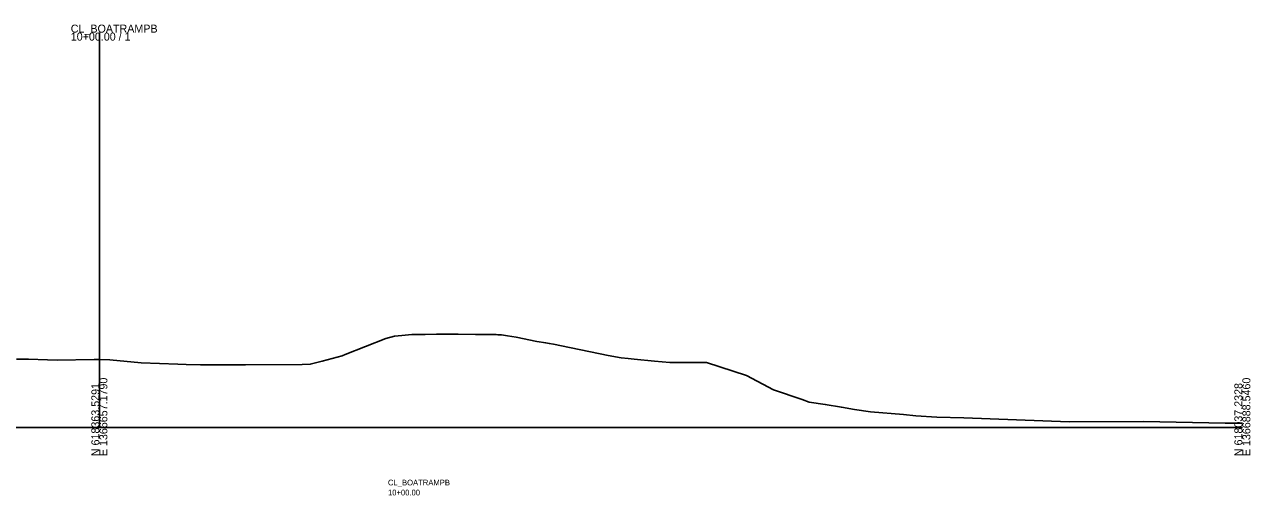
# Model space of a CAD drawing. Extents: x -26 to 803, y -24 to 3192.
# Drawn here: x 373.8 to 802.8, y -23.8 to 141.1 of the extents above; entities that cross this region are included whole.
import ezdxf

# ---------------------------------------------------------------- set-up
doc = ezdxf.new("R2010")
doc.units = 0
for name, color, linetype in [('DESIGN - SHEET - Light Grid', 7, 'Continuous'), ('DESIGN - TYPICAL - Warning Text', 7, 'Continuous'), ('SURVEY - GROUND - Top of Ground', 7, 'Continuous')]:
    doc.layers.add(name, color=color, linetype=linetype)

msp = doc.modelspace()

# ---------------------------------------------------------------- linework, layer by layer
at = {"layer": 'DESIGN - SHEET - Light Grid'}
for p, q in [((400, 0), (400, 138.3)), ((0, 0), (400, 0)), ((400, 0), (800, 0))]:
    msp.add_line(p, q, dxfattribs=at)
at = {"layer": 'SURVEY - GROUND - Top of Ground'}
msp.add_lwpolyline([(370.95, 23.97), (375.17, 23.94), (381.8, 23.71), (385.26, 23.65), (398.23, 23.84), (400, 23.8), (403.65, 23.73), (414.63, 22.64), (427.46, 22.22), (430.4, 22.06), (435.44, 22.03), (451.12, 21.93), (470.93, 22.13), (473.81, 22.15), (477.97, 23.27), (485.02, 25.17), (486.03, 25.65), (500.21, 31.15), (503.27, 32), (505.9, 32.27), (509.33, 32.56), (511.76, 32.63), (512.38, 32.64), (514.05, 32.65), (517.99, 32.68), (523.28, 32.7), (525.51, 32.72), (531.63, 32.64), (538.9, 32.54), (539.41, 32.51), (540.7, 32.45), (542.79, 32.15), (545.86, 31.7), (553.13, 30.15), (556.21, 29.62), (557.43, 29.47), (558.96, 29.18), (561.72, 28.68), (578.07, 25.22), (582.63, 24.45), (585.1, 24.18), (587.14, 23.98), (594.26, 23.22), (599.62, 22.8), (609.75, 22.84), (612.45, 22.75), (626.43, 18.25), (635.92, 13.22), (645.96, 9.81), (648.37, 8.86), (654.04, 8.13), (659.69, 7.11), (664.22, 6.38), (669.9, 5.46), (681.45, 4.59), (685.69, 4.08), (693.07, 3.67), (702.5, 3.41), (739.42, 2), (765.35, 2.08), (793.93, 1.57), (797.9, 1.5), (800, 1.52)], dxfattribs=at)

# ---------------------------------------------------------------- texts
at = {"layer": 'DESIGN - SHEET - Light Grid'}
for s, p in [('CL_BOATRAMPB', (390, 138.3)), ('10+00.00 / 1', (390, 135.5))]:
    msp.add_text(s, height=2.8, dxfattribs=at).set_placement(p)
for s, p in [('E 1366657.1790', (402.8, -10)), ('E 1366888.5460', (802.8, -10)), ('N 618363.5291', (400, -10)), ('N 618037.2328', (800, -10))]:
    msp.add_text(s, height=2.8, rotation=90, dxfattribs=at).set_placement(p)
at = {"layer": 'DESIGN - TYPICAL - Warning Text'}
for s, p in [('CL_BOATRAMPB', (501, -20.25)), ('10+00.00', (501, -23.75))]:
    msp.add_text(s, height=2, dxfattribs=at).set_placement(p)

doc.saveas('drawing.dxf')
